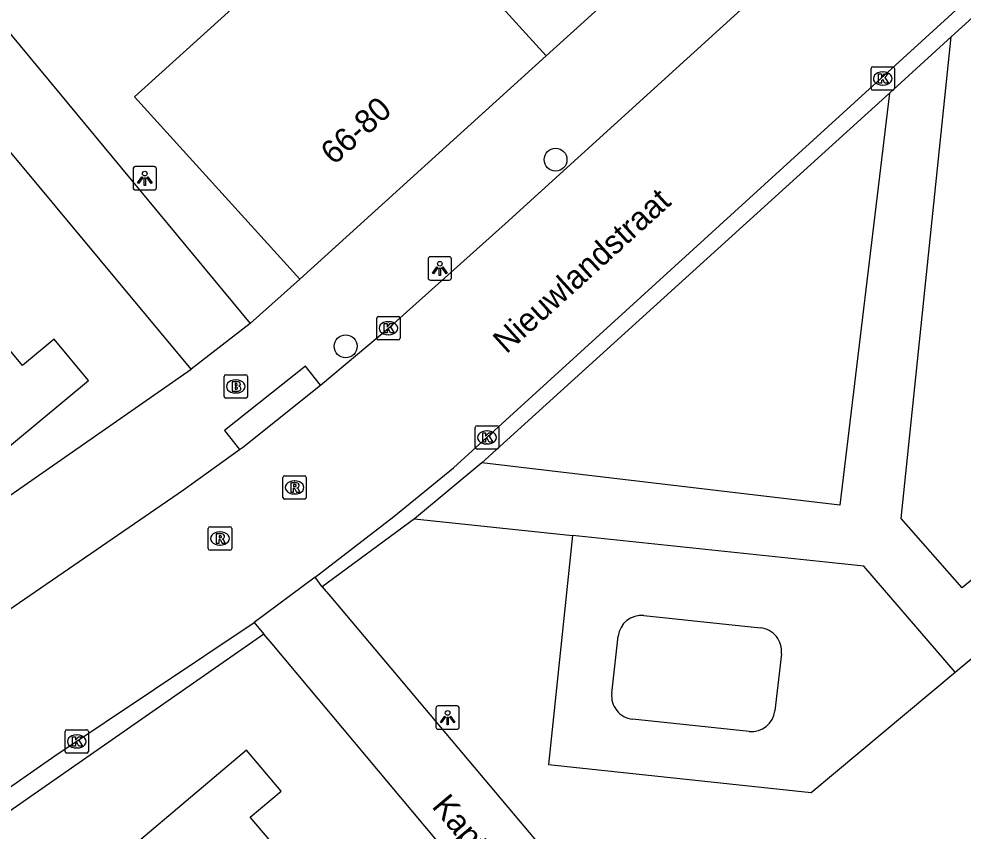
# Model space of a CAD drawing. Extents: x 159888 to 160757, y 384031 to 384746.
# Drawn here: x 160379.36 to 160419.72, y 384187.25 to 384221.95 of the extents above; entities that cross this region are included whole.
import ezdxf

# ---------------------------------------------------------------- set-up
doc = ezdxf.new("R2010")
doc.units = 0
for name, color, linetype in [('IMGEO_Boom', 7, 'Continuous'), ('IMGEO_Brandkraan', 7, 'Continuous'), ('IMGEO_Kolk', 7, 'Continuous'), ('IMGEO_Lichtpunt', 7, 'Continuous'), ('IMGEO_Openbare_ruimte_label', 7, 'Continuous'), ('IMGEO_Pand', 7, 'Continuous'), ('IMGEO_Pand_nummerreeks', 7, 'Continuous'), ('IMGEO_Rijbaan_lokaal_open', 7, 'Continuous'), ('IMGEO_Rioolput', 7, 'Continuous'), ('IMGEO_Voetpad_halfverhard', 7, 'Continuous'), ('IMGEO_Voetpad_open', 7, 'Continuous')]:
    doc.layers.add(name, color=color, linetype=linetype)

msp = doc.modelspace()

# ---------------------------------------------------------------- linework, layer by layer
at = {"layer": 'IMGEO_Boom'}
for centre in [(160402.299, 384215.935), (160393.33, 384207.96)]:
    msp.add_circle(centre, 0.489, dxfattribs=at)
at = {"layer": 'IMGEO_Brandkraan'}
for p, q in [((160388.134, 384205.819), (160388.134, 384206.671)), ((160388.209, 384206.745), (160389.061, 384206.745)), ((160388.622, 384206.525), (160388.647, 384206.525)), ((160389.135, 384206.671), (160389.135, 384205.819)), ((160389.061, 384205.745), (160388.209, 384205.745)), ((160388.645, 384205.965), (160388.62, 384205.965))]:
    msp.add_line(p, q, dxfattribs=at)
for points in [[(160388.134, 384205.819), (160388.134, 384206.671)], [(160388.209, 384206.745), (160389.061, 384206.745)], [(160389.135, 384206.671), (160389.135, 384205.819)], [(160388.482, 384206.445), (160388.482, 384206.045), (160388.695, 384206.045)], [(160388.713, 384206.445), (160388.482, 384206.445)], [(160388.661, 384206.364), (160388.607, 384206.364), (160388.607, 384206.288)], [(160388.607, 384206.288), (160388.66, 384206.288)], [(160388.669, 384206.212), (160388.607, 384206.212), (160388.607, 384206.131)], [(160388.607, 384206.131), (160388.669, 384206.131)], [(160389.061, 384205.745), (160388.209, 384205.745)]]:
    msp.add_lwpolyline(points, dxfattribs=at)
for centre, radius, start, end in [((160388.211, 384206.669), 0.0765, 91.552, 178.448), ((160388.211, 384206.669), 0.0765, 91.552, 178.448), ((160389.059, 384206.669), 0.0765, 1.552, 88.448), ((160389.059, 384206.669), 0.0765, 1.552, 88.448), ((160388.662, 384206.326), 0.0379, 267.8285, 90.9355), ((160388.67, 384206.171), 0.0404, 269.8759, 90.5077), ((160388.717, 384206.3), 0.145, 59.4692, 91.5367), ((160388.742, 384206.347), 0.0922, 285.5137, 58.1501), ((160388.747, 384206.155), 0.105, 301.3115, 78.989), ((160388.211, 384205.821), 0.0765, 181.552, 268.448), ((160388.211, 384205.821), 0.0765, 181.552, 268.448), ((160388.701, 384206.296), 0.251, 268.6676, 293.5347), ((160389.059, 384205.821), 0.0765, 271.552, 358.448), ((160389.059, 384205.821), 0.0765, 271.552, 358.448)]:
    msp.add_arc(centre, radius, start, end, dxfattribs=at)
for centre, major_axis, ratio, start_param, end_param in [((160388.621, 384206.245), (-0.387, 0.002), 0.722429, 4.712389, 7.853982), ((160388.646, 384206.245), (-0.39, 0.002), 0.717154, 1.570796, 4.712389)]:
    msp.add_ellipse(centre, major_axis=major_axis, ratio=ratio, start_param=start_param, end_param=end_param, dxfattribs=at)
at = {"layer": 'IMGEO_Kolk'}
for p, q in [((160415.78, 384218.975), (160415.78, 384219.827)), ((160415.855, 384219.901), (160416.707, 384219.901)), ((160416.781, 384219.827), (160416.781, 384218.975)), ((160416.268, 384219.681), (160416.293, 384219.681)), ((160416.291, 384219.121), (160416.266, 384219.121)), ((160416.707, 384218.901), (160415.855, 384218.901)), ((160394.656, 384208.304), (160394.656, 384209.156)), ((160394.731, 384209.23), (160395.583, 384209.23)), ((160395.144, 384209.01), (160395.169, 384209.01)), ((160395.657, 384209.156), (160395.657, 384208.304)), ((160395.583, 384208.23), (160394.731, 384208.23)), ((160395.167, 384208.45), (160395.142, 384208.45)), ((160398.868, 384203.64), (160398.868, 384204.492)), ((160398.943, 384204.566), (160399.795, 384204.566)), ((160399.869, 384204.492), (160399.869, 384203.64)), ((160399.356, 384204.346), (160399.381, 384204.346)), ((160399.379, 384203.786), (160399.354, 384203.786)), ((160399.795, 384203.566), (160398.943, 384203.566)), ((160381.413, 384191.578), (160382.265, 384191.578)), ((160381.338, 384190.652), (160381.338, 384191.504)), ((160381.826, 384191.358), (160381.851, 384191.358)), ((160382.339, 384191.504), (160382.339, 384190.652)), ((160381.849, 384190.798), (160381.824, 384190.798)), ((160382.265, 384190.578), (160381.413, 384190.578))]:
    msp.add_line(p, q, dxfattribs=at)
for points in [[(160415.78, 384218.975), (160415.78, 384219.827)], [(160415.855, 384219.901), (160416.707, 384219.901)], [(160416.781, 384219.827), (160416.781, 384218.975)], [(160416.101, 384219.601), (160416.224, 384219.601), (160416.224, 384219.45), (160416.354, 384219.601), (160416.518, 384219.601), (160416.372, 384219.45), (160416.525, 384219.201), (160416.373, 384219.201), (160416.288, 384219.365), (160416.224, 384219.298), (160416.224, 384219.201), (160416.101, 384219.201), (160416.101, 384219.601)], [(160416.707, 384218.901), (160415.855, 384218.901)], [(160394.656, 384208.304), (160394.656, 384209.156)], [(160394.731, 384209.23), (160395.583, 384209.23)], [(160394.977, 384208.93), (160395.1, 384208.93), (160395.1, 384208.779), (160395.23, 384208.93), (160395.394, 384208.93), (160395.248, 384208.779), (160395.401, 384208.53), (160395.249, 384208.53), (160395.164, 384208.694), (160395.1, 384208.627), (160395.1, 384208.53), (160394.977, 384208.53), (160394.977, 384208.93)], [(160395.657, 384209.156), (160395.657, 384208.304)], [(160395.583, 384208.23), (160394.731, 384208.23)], [(160398.868, 384203.64), (160398.868, 384204.492)], [(160398.943, 384204.566), (160399.795, 384204.566)], [(160399.869, 384204.492), (160399.869, 384203.64)], [(160399.189, 384204.266), (160399.312, 384204.266), (160399.312, 384204.115), (160399.442, 384204.266), (160399.606, 384204.266), (160399.46, 384204.115), (160399.613, 384203.866), (160399.461, 384203.866), (160399.376, 384204.03), (160399.312, 384203.963), (160399.312, 384203.866), (160399.189, 384203.866), (160399.189, 384204.266)], [(160399.795, 384203.566), (160398.943, 384203.566)], [(160381.413, 384191.578), (160382.265, 384191.578)], [(160381.338, 384190.652), (160381.338, 384191.504)], [(160381.659, 384191.278), (160381.782, 384191.278), (160381.782, 384191.127), (160381.912, 384191.278), (160382.076, 384191.278), (160381.93, 384191.127), (160382.083, 384190.878), (160381.931, 384190.878), (160381.846, 384191.042), (160381.782, 384190.975), (160381.782, 384190.878), (160381.659, 384190.878), (160381.659, 384191.278)], [(160382.339, 384191.504), (160382.339, 384190.652)], [(160382.265, 384190.578), (160381.413, 384190.578)]]:
    msp.add_lwpolyline(points, dxfattribs=at)
for centre, start, end in [((160415.857, 384219.825), 91.552, 178.448), ((160415.857, 384219.825), 91.552, 178.448), ((160416.705, 384219.825), 1.552, 88.448), ((160416.705, 384219.825), 1.552, 88.448), ((160415.857, 384218.977), 181.552, 268.448), ((160415.857, 384218.977), 181.552, 268.448), ((160416.705, 384218.977), 271.552, 358.448), ((160416.705, 384218.977), 271.552, 358.448), ((160394.733, 384209.154), 91.552, 178.448), ((160394.733, 384209.154), 91.552, 178.448), ((160395.581, 384209.154), 1.552, 88.448), ((160395.581, 384209.154), 1.552, 88.448), ((160394.733, 384208.306), 181.552, 268.448), ((160394.733, 384208.306), 181.552, 268.448), ((160395.581, 384208.306), 271.552, 358.448), ((160395.581, 384208.306), 271.552, 358.448), ((160398.945, 384204.49), 91.552, 178.448), ((160398.945, 384204.49), 91.552, 178.448), ((160399.793, 384204.49), 1.552, 88.448), ((160399.793, 384204.49), 1.552, 88.448), ((160398.945, 384203.642), 181.552, 268.448), ((160398.945, 384203.642), 181.552, 268.448), ((160399.793, 384203.642), 271.552, 358.448), ((160399.793, 384203.642), 271.552, 358.448), ((160381.415, 384191.502), 91.552, 178.448), ((160381.415, 384191.502), 91.552, 178.448), ((160382.263, 384191.502), 1.552, 88.448), ((160382.263, 384191.502), 1.552, 88.448), ((160381.415, 384190.654), 181.552, 268.448), ((160381.415, 384190.654), 181.552, 268.448), ((160382.263, 384190.654), 271.552, 358.448), ((160382.263, 384190.654), 271.552, 358.448)]:
    msp.add_arc(centre, 0.0765, start, end, dxfattribs=at)
for centre, major_axis, ratio, start_param, end_param in [((160416.267, 384219.401), (-0.387, 0.002), 0.722429, 4.712389, 7.853982), ((160416.292, 384219.401), (-0.39, 0.002), 0.717154, 1.570796, 4.712389), ((160395.143, 384208.73), (-0.387, 0.002), 0.722429, 4.712389, 7.853982), ((160395.168, 384208.73), (-0.39, 0.002), 0.717154, 1.570796, 4.712389), ((160399.355, 384204.066), (-0.387, 0.002), 0.722429, 4.712389, 7.853982), ((160399.38, 384204.066), (-0.39, 0.002), 0.717154, 1.570796, 4.712389), ((160381.825, 384191.078), (-0.387, 0.002), 0.722429, 4.712389, 7.853982), ((160381.85, 384191.078), (-0.39, 0.002), 0.717154, 1.570796, 4.712389)]:
    msp.add_ellipse(centre, major_axis=major_axis, ratio=ratio, start_param=start_param, end_param=end_param, dxfattribs=at)
at = {"layer": 'IMGEO_Lichtpunt'}
for p, q in [((160384.246, 384215.54), (160384.246, 384214.733)), ((160384.246, 384215.54), (160384.246, 384214.733)), ((160385.148, 384215.635), (160384.34, 384215.635)), ((160385.148, 384215.635), (160384.34, 384215.635)), ((160385.242, 384214.733), (160385.242, 384215.54)), ((160385.242, 384214.733), (160385.242, 384215.54)), ((160384.34, 384214.639), (160385.148, 384214.639)), ((160384.34, 384214.639), (160385.148, 384214.639)), ((160397.757, 384211.784), (160396.949, 384211.784)), ((160397.757, 384211.784), (160396.949, 384211.784)), ((160396.855, 384211.689), (160396.855, 384210.882)), ((160396.855, 384211.689), (160396.855, 384210.882)), ((160397.851, 384210.882), (160397.851, 384211.689)), ((160397.851, 384210.882), (160397.851, 384211.689)), ((160396.949, 384210.788), (160397.757, 384210.788)), ((160396.949, 384210.788), (160397.757, 384210.788)), ((160397.189, 384192.498), (160397.189, 384191.691)), ((160397.189, 384192.498), (160397.189, 384191.691)), ((160398.091, 384192.593), (160397.283, 384192.593)), ((160398.091, 384192.593), (160397.283, 384192.593)), ((160398.185, 384191.691), (160398.185, 384192.498)), ((160398.185, 384191.691), (160398.185, 384192.498)), ((160397.283, 384191.597), (160398.091, 384191.597)), ((160397.283, 384191.597), (160398.091, 384191.597))]:
    msp.add_line(p, q, dxfattribs=at)
for points in [[(160384.62, 384215.204), (160384.659, 384215.176), (160384.471, 384214.914), (160384.433, 384214.941), (160384.62, 384215.204)], [(160384.722, 384215.156), (160384.769, 384215.156), (160384.769, 384214.834), (160384.722, 384214.834), (160384.722, 384215.156)], [(160384.832, 384215.176), (160384.87, 384215.203), (160385.057, 384214.941), (160385.018, 384214.913), (160384.832, 384215.176)], [(160397.229, 384211.353), (160397.268, 384211.325), (160397.08, 384211.063), (160397.042, 384211.09), (160397.229, 384211.353)], [(160397.441, 384211.325), (160397.479, 384211.352), (160397.666, 384211.09), (160397.627, 384211.062), (160397.441, 384211.325)], [(160397.331, 384211.305), (160397.378, 384211.305), (160397.378, 384210.983), (160397.331, 384210.983), (160397.331, 384211.305)], [(160397.563, 384192.162), (160397.602, 384192.134), (160397.414, 384191.872), (160397.376, 384191.899), (160397.563, 384192.162)], [(160397.665, 384192.114), (160397.712, 384192.114), (160397.712, 384191.792), (160397.665, 384191.792), (160397.665, 384192.114)], [(160397.775, 384192.134), (160397.813, 384192.161), (160398, 384191.899), (160397.961, 384191.871), (160397.775, 384192.134)]]:
    msp.add_lwpolyline(points, dxfattribs=at)
for centre in [(160384.745, 384215.338), (160397.354, 384211.487), (160397.688, 384192.296)]:
    msp.add_circle(centre, 0.0994, dxfattribs=at)
for centre, start, end in [((160384.34, 384215.54), 90, 180), ((160384.34, 384215.54), 90, 180), ((160385.148, 384215.54), 0, 90), ((160385.148, 384215.54), 0, 90), ((160384.34, 384214.733), 180, 270), ((160384.34, 384214.733), 180, 270), ((160385.148, 384214.733), 270, 0), ((160385.148, 384214.733), 270, 360), ((160396.949, 384211.689), 90, 180), ((160396.949, 384211.689), 90, 180), ((160397.757, 384211.689), 0, 90), ((160397.757, 384211.689), 0, 90), ((160396.949, 384210.882), 180, 270), ((160396.949, 384210.882), 180, 270), ((160397.757, 384210.882), 270, 0), ((160397.757, 384210.882), 270, 360), ((160397.283, 384192.498), 90, 180), ((160397.283, 384192.498), 90, 180), ((160398.091, 384192.498), 0, 90), ((160398.091, 384192.498), 0, 90), ((160397.283, 384191.691), 180, 270), ((160397.283, 384191.691), 180, 270), ((160398.091, 384191.691), 270, 0), ((160398.091, 384191.691), 270, 360)]:
    msp.add_arc(centre, 0.0946, start, end, dxfattribs=at)
at = {"layer": 'IMGEO_Pand'}
for points in [[(160401.898, 384220.364), (160412.421, 384229.898)], [(160394.835, 384228.14), (160384.306, 384218.612), (160391.374, 384210.83)], [(160401.898, 384220.364), (160394.835, 384228.14)], [(160391.374, 384210.83), (160401.898, 384220.364)], [(160364.535, 384213.771), (160373.901, 384202.49), (160373.52, 384202.174), (160374.996, 384200.397), (160382.336, 384206.493), (160380.867, 384208.263), (160379.522, 384207.146), (160370.151, 384218.433)], [(160398.757, 384176.656), (160389.246, 384187.843), (160390.568, 384188.957), (160389.098, 384190.7), (160381.81, 384184.558), (160383.291, 384182.8), (160383.736, 384183.175), (160393.207, 384171.937)]]:
    msp.add_lwpolyline(points, dxfattribs=at)
at = {"layer": 'IMGEO_Rijbaan_lokaal_open'}
for points in [[(160392.259, 384206.298), (160395.244, 384208.801), (160400.149, 384213.193), (160440.675, 384250), (160445.18, 384254.092)], [(160392.025, 384198.09), (160395.382, 384200.689), (160397.932, 384202.765), (160449.329, 384249.596)], [(160388.797, 384203.549), (160388.92, 384203.637), (160392.259, 384206.298)], [(160373.781, 384193.161), (160376.559, 384195.084), (160386.395, 384201.834), (160388.797, 384203.549)], [(160392.025, 384198.09), (160389.416, 384196.161)], [(160374.745, 384186.163), (160375.465, 384186.68), (160380.904, 384190.464), (160389.416, 384196.161)]]:
    msp.add_lwpolyline(points, dxfattribs=at)
at = {"layer": 'IMGEO_Rioolput'}
for p, q in [((160390.645, 384201.505), (160390.645, 384202.357)), ((160390.72, 384202.431), (160391.572, 384202.431)), ((160391.133, 384202.211), (160391.158, 384202.211)), ((160391.646, 384202.357), (160391.646, 384201.505)), ((160391.572, 384201.431), (160390.72, 384201.431)), ((160391.156, 384201.651), (160391.131, 384201.651)), ((160387.457, 384199.323), (160387.457, 384200.175)), ((160387.532, 384200.249), (160388.384, 384200.249)), ((160388.458, 384200.175), (160388.458, 384199.323)), ((160387.945, 384200.029), (160387.97, 384200.029)), ((160388.384, 384199.249), (160387.532, 384199.249)), ((160387.968, 384199.469), (160387.943, 384199.469))]:
    msp.add_line(p, q, dxfattribs=at)
for points in [[(160390.645, 384201.505), (160390.645, 384202.357)], [(160390.72, 384202.431), (160391.572, 384202.431)], [(160391.234, 384202.129), (160390.982, 384202.131), (160390.982, 384201.731)], [(160391.646, 384202.357), (160391.646, 384201.505)], [(160390.982, 384201.731), (160391.106, 384201.731), (160391.106, 384201.893), (160391.117, 384201.893)], [(160391.16, 384202.05), (160391.106, 384202.05), (160391.106, 384201.969)], [(160391.106, 384201.969), (160391.158, 384201.969)], [(160391.164, 384201.864), (160391.235, 384201.731), (160391.375, 384201.731), (160391.31, 384201.857)], [(160391.572, 384201.431), (160390.72, 384201.431)], [(160387.457, 384199.323), (160387.457, 384200.175)], [(160387.532, 384200.249), (160388.384, 384200.249)], [(160388.458, 384200.175), (160388.458, 384199.323)], [(160388.046, 384199.947), (160387.794, 384199.949), (160387.794, 384199.549)], [(160387.794, 384199.549), (160387.918, 384199.549), (160387.918, 384199.711), (160387.929, 384199.711)], [(160387.972, 384199.868), (160387.918, 384199.868), (160387.918, 384199.787)], [(160387.918, 384199.787), (160387.97, 384199.787)], [(160387.976, 384199.682), (160388.047, 384199.549), (160388.187, 384199.549), (160388.122, 384199.675)], [(160388.384, 384199.249), (160387.532, 384199.249)]]:
    msp.add_lwpolyline(points, dxfattribs=at)
for centre, radius, start, end in [((160390.722, 384202.355), 0.0765, 91.552, 178.448), ((160390.722, 384202.355), 0.0765, 91.552, 178.448), ((160391.233, 384202.019), 0.109, 350.3612, 89.416), ((160391.57, 384202.355), 0.0765, 1.552, 88.448), ((160391.57, 384202.355), 0.0765, 1.552, 88.448), ((160391.116, 384201.84), 0.0533, 26.0293, 88.6989), ((160391.142, 384202.158), 0.19, 274.7715, 282.9687), ((160391.166, 384201.954), 0.0964, 77.0061, 93.1865), ((160391.18, 384202.011), 0.0378, 276.6634, 79.6772), ((160391.231, 384202.019), 0.112, 277.5842, 350.9817), ((160391.215, 384201.804), 0.108, 29.5134, 73.7905), ((160390.722, 384201.507), 0.0765, 181.552, 268.448), ((160390.722, 384201.507), 0.0765, 181.552, 268.448), ((160391.57, 384201.507), 0.0765, 271.552, 358.448), ((160391.57, 384201.507), 0.0765, 271.552, 358.448), ((160387.534, 384200.173), 0.0765, 91.552, 178.448), ((160387.534, 384200.173), 0.0765, 91.552, 178.448), ((160388.382, 384200.173), 0.0765, 1.552, 88.448), ((160388.382, 384200.173), 0.0765, 1.552, 88.448), ((160387.928, 384199.658), 0.0533, 26.0293, 88.6989), ((160387.954, 384199.976), 0.19, 274.7715, 282.9687), ((160387.978, 384199.772), 0.0964, 77.0061, 93.1865), ((160387.992, 384199.829), 0.0378, 276.6634, 79.6772), ((160388.045, 384199.837), 0.109, 350.3612, 89.416), ((160388.043, 384199.837), 0.112, 277.5842, 350.9817), ((160388.027, 384199.622), 0.108, 29.5134, 73.7905), ((160387.534, 384199.325), 0.0765, 181.552, 268.448), ((160387.534, 384199.325), 0.0765, 181.552, 268.448), ((160388.382, 384199.325), 0.0765, 271.552, 358.448), ((160388.382, 384199.325), 0.0765, 271.552, 358.448)]:
    msp.add_arc(centre, radius, start, end, dxfattribs=at)
for centre, major_axis, ratio, start_param, end_param in [((160391.132, 384201.931), (-0.387, 0.002), 0.722429, 4.712389, 7.853982), ((160391.157, 384201.931), (-0.39, 0.002), 0.717154, 1.570796, 4.712389), ((160387.944, 384199.749), (-0.387, 0.002), 0.722429, 4.712389, 7.853982), ((160387.969, 384199.749), (-0.39, 0.002), 0.717154, 1.570796, 4.712389)]:
    msp.add_ellipse(centre, major_axis=major_axis, ratio=ratio, start_param=start_param, end_param=end_param, dxfattribs=at)
at = {"layer": 'IMGEO_Voetpad_halfverhard'}
for points in [[(160403.03, 384199.875), (160401.999, 384190.089), (160413.229, 384188.902), (160419.38, 384194.033)], [(160406.074, 384196.458), (160411.06, 384195.931)], [(160404.7, 384193.138), (160404.976, 384195.576)], [(160411.949, 384194.824), (160411.673, 384192.386)], [(160410.574, 384191.504), (160405.588, 384192.031)]]:
    msp.add_lwpolyline(points, dxfattribs=at)
for centre, radius, start, end in [((160405.969, 384195.464), 1, 83.9844, 173.5639), ((160410.954, 384194.936), 1.001, 353.6016, 83.9323), ((160405.695, 384193.026), 1.001, 173.6059, 263.865), ((160410.678, 384192.5), 1.001, 264.0248, 353.4726)]:
    msp.add_arc(centre, radius, start, end, dxfattribs=at)
at = {"layer": 'IMGEO_Voetpad_open'}
for points in [[(160445.123, 384244.678), (160419.212, 384221.179)], [(160364.144, 384239.222), (160389.244, 384208.933)], [(160386.728, 384206.983), (160361.616, 384237.146)], [(160461.362, 384232.282), (160419.671, 384197.644), (160417.064, 384200.601), (160419.212, 384221.179)], [(160419.38, 384194.033), (160462.762, 384230.216)], [(160419.212, 384221.179), (160416.564, 384218.778)], [(160416.564, 384218.778), (160414.45, 384201.178), (160399.146, 384202.981)], [(160416.564, 384218.778), (160399.146, 384202.981)], [(160389.244, 384208.933), (160391.374, 384210.83)], [(160389.244, 384208.933), (160386.728, 384206.983)], [(160368.445, 384194.271), (160386.728, 384206.983)], [(160392.259, 384206.298), (160391.613, 384207.113), (160388.151, 384204.364), (160388.797, 384203.549)], [(160399.146, 384202.981), (160396.267, 384200.587)], [(160396.267, 384200.587), (160392.322, 384197.688)], [(160396.267, 384200.587), (160403.03, 384199.875)], [(160419.38, 384194.033), (160415.475, 384198.563), (160403.03, 384199.875)], [(160392.322, 384197.688), (160392.025, 384198.09)], [(160392.322, 384197.688), (160392.679, 384197.264), (160418.154, 384167.028)], [(160389.416, 384196.161), (160389.837, 384195.662)], [(160389.837, 384195.662), (160374.65, 384185.092)], [(160415.675, 384164.808), (160415.333, 384165.23), (160390.189, 384195.245), (160389.837, 384195.662)]]:
    msp.add_lwpolyline(points, dxfattribs=at)

# ---------------------------------------------------------------- texts
at = {"layer": 'IMGEO_Openbare_ruimte_label'}
for s, rotation, p in [('Nieuwlandstraat', 42.2428, (160400.195, 384207.608)), ('Kapteynstraat', 309.8863, (160396.976, 384188.289))]:
    msp.add_text(s, height=1, rotation=rotation, dxfattribs=at).set_placement(p)
at = {"layer": 'IMGEO_Pand_nummerreeks'}
msp.add_text('66-80', height=1, rotation=42.0114, dxfattribs=at).set_placement((160392.825, 384215.669))

doc.saveas('drawing.dxf')
